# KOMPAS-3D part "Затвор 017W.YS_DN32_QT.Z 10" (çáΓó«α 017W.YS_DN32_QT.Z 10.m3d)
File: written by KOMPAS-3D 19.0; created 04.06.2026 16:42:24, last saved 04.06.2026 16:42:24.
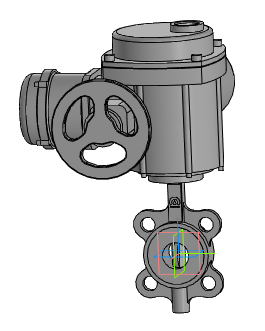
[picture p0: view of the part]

Document properties: Автор: Энергия; Полное имя файла: ..\..\..\3d для проектировщиков\017W разные\x.x Тип 017W.Y(S) Затвор дисковый поворотный межфланцевый\Затвор 017W.Y(S)_DN32-DN450_QT.Z\Затвор 017W.YS_DN32_QT.Z 10.a3d

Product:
- Part/product: Затвор 017W.YS_DN32_QT.Z 10
    Масса: 29.5941

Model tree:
1. Операция без истории:1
